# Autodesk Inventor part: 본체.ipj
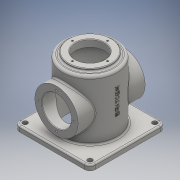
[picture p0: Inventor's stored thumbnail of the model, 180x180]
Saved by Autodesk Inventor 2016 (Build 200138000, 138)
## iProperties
Created: 2019-08
Part Number: 본체.ipj
Material: 일반
Document SubType Name: Modeling
Designer: user
Density: 1 g/cm^3
Appearance: 기본값
Author: user
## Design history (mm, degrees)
sketch "스케치1"
  geometry: L1 (-70, -70)-(70, -70); L2 (70, -70)-(70, 70); L3 (70, 70)-(-70, 70); L4 (-70, 70)-(-70, -70); L5 (-70, -70)-(70, 70); L6 (70, -70)-(-70, 70); 1 further point
  constraints: 12 end point, 2 midpoint, 2 parallel, 1 horizontal, 1 perpendicular
  dimensions: "d0" = 140 distance of L3.end L2.end; "d1" = 140 distance of L2.end L1.end
extrude "돌출1" new body sketch "스케치1" distance "d2" = 10; taper "d3" = 0 deg
sketch "스케치2"
  geometry: C1 r 50 at (0, 0); 1 further point
  constraints: 1 centre point, 1 coincident
  dimensions: "d4" = 100 diameter of C1
extrude "돌출2" join sketch "스케치2" distance "d5" = 110; taper "d6" = 0 deg
node "작업 평면1"
sketch "스케치4"
  geometry: L1 (-50, 10)-(50, 10) reference; L2 (70, 0)-(-70, 0) reference; C1 r 40 at (0, 60); 1 further point
  constraints: 1 centre point, 1 vertical alignment
  dimensions: "d8" = 80 diameter of C1; "d89" = 60 distance from line of L2 C1.centre
extrude "돌출3" join sketch "스케치4" stored distance "d10" = 110; taper "d11" = 0 deg
sketch "스케치5"
  geometry: C1 r 27 at (0, 0); 1 further point
  constraints: 1 centre point
  dimensions: "d12" = 54 diameter of C1
extrude "돌출4" cut sketch "스케치5" stored distance "d13" = 110; taper "d14" = 0 deg
sketch "스케치6" dims "d15" = 65
  geometry: 3 further points
  constraints: 1 vertical alignment, 2 other
hole "구멍1" sketch "스케치6" at (0, 32.5) diameter "d16" = 3.242; stored, may be unused: countersink angle "d20" = 90 deg, drill point angle "d22" = 118 deg; dims "d17" = 8, "d18" = 4, "d19" = 2, "d21" = 10
sketch "스케치7"
  geometry: C1 r 40 at (0, 0); 1 further point
  constraints: 1 centre point, 1 coincident
  dimensions: "d26" = 80 diameter of C1
extrude "돌출5" join sketch "스케치7" distance "d27" = 5; taper "d28" = 0 deg
sketch "스케치10"
  geometry: C1 r 27 at (0, 0); 1 further point
  constraints: 1 centre point, 1 coincident
  dimensions: "d29" = 54 diameter of C1
extrude "돌출6" cut sketch "스케치10" distance "d30" = 13; taper "d31" = 0 deg
sketch "스케치11" dims "d32" = 65
  geometry: 3 further points
  constraints: 1 coincident, 1 vertical alignment, 2 other
hole "구멍2" sketch "스케치11" at (0, 32.5) diameter "d33" = 3.242; stored, may be unused: countersink angle "d37" = 90 deg, drill point angle "d39" = 118 deg; dims "d34" = 8, "d35" = 4, "d36" = 2, "d38" = 10
fillet "모깎기1" dims "d43" = 10
hole "구멍3" diameter "d46" = 9; stored, may be unused: countersink angle "d50" = 90 deg, drill point angle "d52" = 0 deg; dims "d47" = 8, "d48" = 4, "d49" = 2, "d51" = 9, "d87" = 10, "d88" = 10
sketch "스케치12"
  geometry: C1 r 45 at (0, 0); 1 further point
  constraints: 1 centre point, 1 coincident
  dimensions: "d59" = 90 diameter of C1
extrude "돌출7" cut sketch "스케치12" distance "d60" = 112; taper "d61" = 0 deg
chamfer "모따기2" distance "d65" = 1; stored, may be unused: second distance "d66" = 2, angle "d67" = 45 deg
chamfer "모따기3" distance "d68" = 1; stored, may be unused: second distance "d69" = 2, angle "d70" = 45 deg
fillet "모깎기2" dims "d71" = 3
fillet "모깎기3" dims "d72" = 5
fillet "모깎기4" dims "d73" = 3
chamfer "모따기4" distance "d74" = 1; stored, may be unused: second distance "d75" = 2, angle "d76" = 45 deg
fillet "모깎기5" dims "d77" = 3
node "작업 평면5"
node "작업 평면6"
sketch "스케치19" dims "d0" = 140, "d1" = 140
  geometry: 2 further points
  constraints: 1 vertical alignment, 1 other
  dimensions: "d90" = 70 distance of point (0, 70) point (0, 0)
feature "엠보싱2" sketch "스케치19" dims "d0" = 140, "d1" = 140, "d85" = 1, "d86" = 0
node "솔리드1"
mirror "대칭1"
pattern_circular "원형 패턴1" dims angle "d24" = 360 deg
mirror "대칭2"
pattern_circular "원형 패턴2" dims angle "d41" = 360 deg
pattern_linear "직사각형 패턴1" dims "d55" = 120
other parameters: "d7" = -62, "d83" = 99.5, "d84" = 75
